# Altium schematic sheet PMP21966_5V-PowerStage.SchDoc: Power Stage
size 431 x 279 mm; Date: Not shown in title block; ApprovedBy: Not shown in title block; CheckedBy: Not shown in title block; Author: Not shown in title block; CompanyName: Not shown in title block; DrawnBy: Tiger Z; Engineer: Not shown in title block; Organization: Not shown in title block; Address1: Not shown in title block; Address2: Not shown in title block; Address3: Not shown in title block; Address4: Not shown in title block; DocumentNumber: 4; Revision: Use project parameter SCH_Rev; SheetNumber: 2; SheetTotal: 3; PageSetup: Record=PageOptions¦CenterHorizontal=True¦CenterVertical=True¦PrintScale=1.00¦XCorrection=1.00¦YCorrection=1.00¦PrintKind=0¦BorderSize=5000000¦LeftOffset=0¦BottomOffset=0¦Orientation=2¦PaperLength=1000¦PaperWidth=1000¦Scale=100¦PaperSource=15¦PrintQuality=600¦MediaType=1¦DitherType=10¦PaperKind=Letter¦PrintScaleMode=1
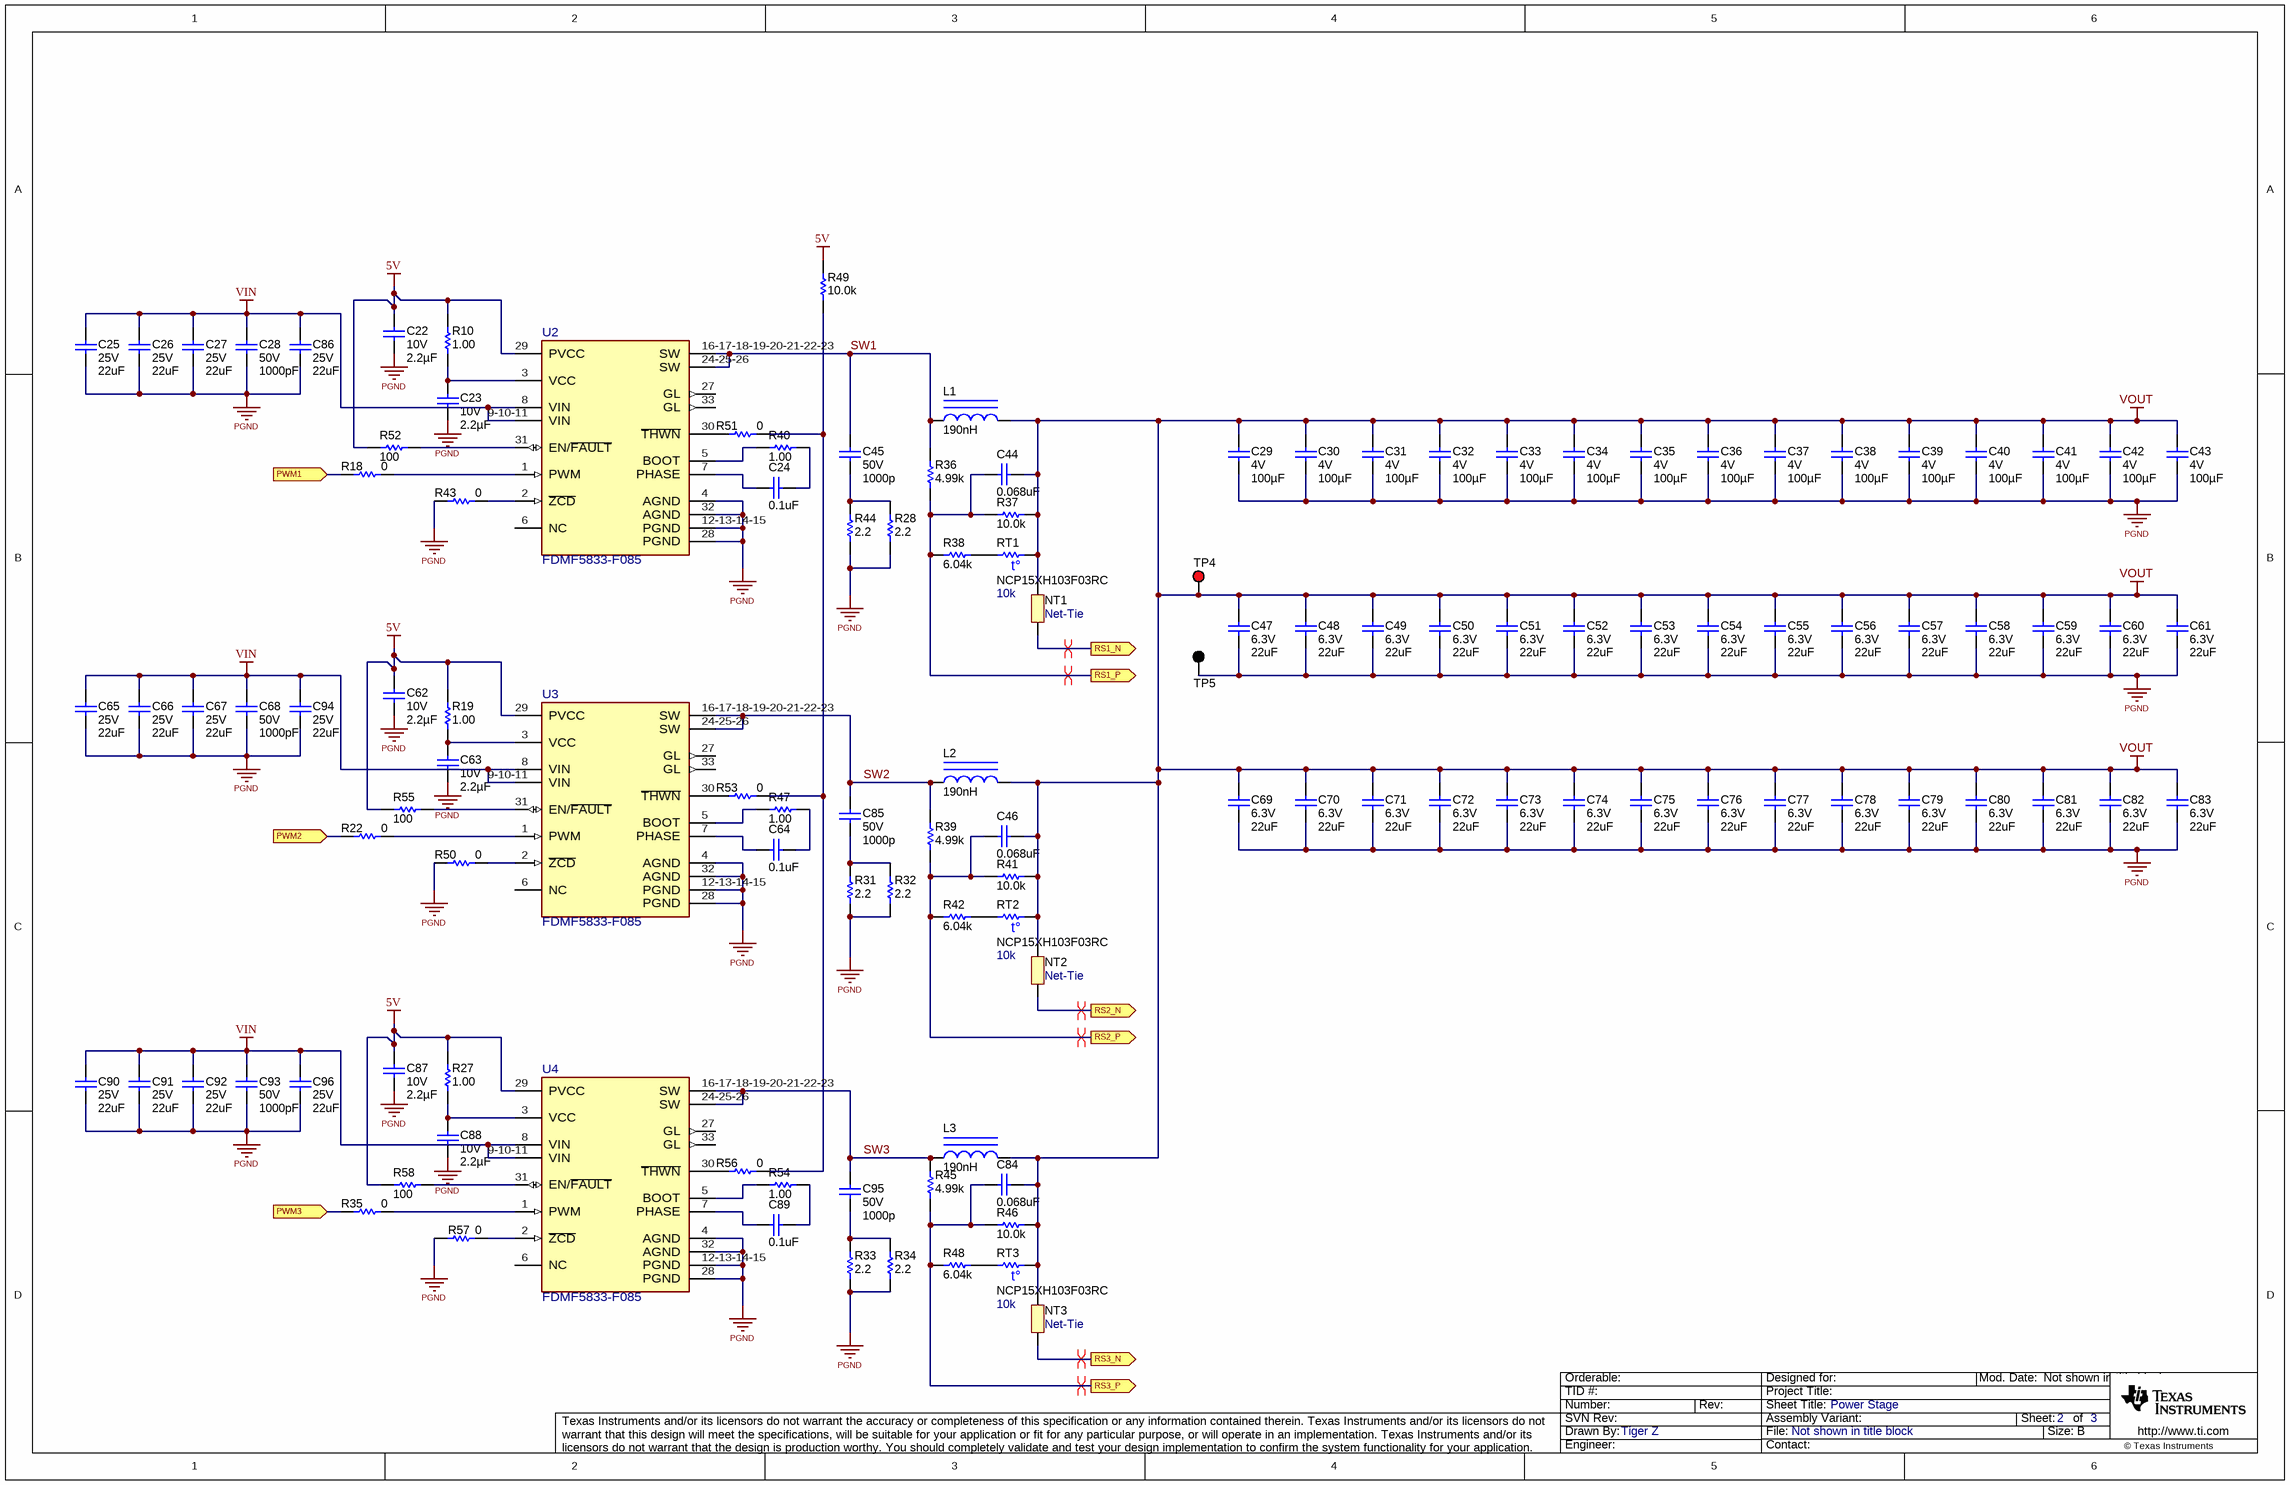
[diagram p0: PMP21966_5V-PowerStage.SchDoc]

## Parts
C22  VDC_V: 10V  ValueDisplayed: 2.2µF  [0603S]  (hidden comment: GRM188R71A225KE15J)
C23  VDC_V: 10V  ValueDisplayed: 2.2µF  [0603S]  (hidden comment: GRM188R71A225KE15J)
C24  ValueDisplayed: 0.1uF  [0402S]  (hidden comment: CGA2B3X7R1H104K050BB)
C25  VDC_V: 25V  ValueDisplayed: 22uF  [1210_270]  (hidden comment: TMK325B7226KMHT)
C26  VDC_V: 25V  ValueDisplayed: 22uF  [1210_270]  (hidden comment: TMK325B7226KMHT)
C27  VDC_V: 25V  ValueDisplayed: 22uF  [1210_270]  (hidden comment: TMK325B7226KMHT)
C28  VDC_V: 50V  ValueDisplayed: 1000pF  [0402S]  (hidden comment: GRM155R71H102KA01D)
C29  VDC_V: 4V  ValueDisplayed: 100µF  [1210_280]  (hidden comment: GCM32ED70G107M)
C30  VDC_V: 4V  ValueDisplayed: 100µF  [1210_280]  (hidden comment: GCM32ED70G107M)
C31  VDC_V: 4V  ValueDisplayed: 100µF  [1210_280]  (hidden comment: GCM32ED70G107M)
C32  VDC_V: 4V  ValueDisplayed: 100µF  [1210_280]  (hidden comment: GCM32ED70G107M)
C33  VDC_V: 4V  ValueDisplayed: 100µF  [1210_280]  (hidden comment: GCM32ED70G107M)
C34  VDC_V: 4V  ValueDisplayed: 100µF  [1210_280]  (hidden comment: GCM32ED70G107M)
C35  VDC_V: 4V  ValueDisplayed: 100µF  [1210_280]  (hidden comment: GCM32ED70G107M)
C36  VDC_V: 4V  ValueDisplayed: 100µF  [1210_280]  (hidden comment: GCM32ED70G107M)
C37  VDC_V: 4V  ValueDisplayed: 100µF  [1210_280]  (hidden comment: GCM32ED70G107M)
C38  VDC_V: 4V  ValueDisplayed: 100µF  [1210_280]  (hidden comment: GCM32ED70G107M)
C39  VDC_V: 4V  ValueDisplayed: 100µF  [1210_280]  (hidden comment: GCM32ED70G107M)
C40  VDC_V: 4V  ValueDisplayed: 100µF  [1210_280]  (hidden comment: GCM32ED70G107M)
C41  VDC_V: 4V  ValueDisplayed: 100µF  [1210_280]  (hidden comment: GCM32ED70G107M)
C42  VDC_V: 4V  ValueDisplayed: 100µF  [1210_280]  (hidden comment: GCM32ED70G107M)
C43  VDC_V: 4V  ValueDisplayed: 100µF  [1210_280]  (hidden comment: GCM32ED70G107M)
C44  ValueDisplayed: 0.068uF  [0402S]  (hidden comment: C1005X7R1H683K050BB)
C45  VDC_V: 50V  ValueDisplayed: 1000p  [0402S]  (hidden comment: GRM1555C1H102FA01D)
C46  ValueDisplayed: 0.068uF  [0402S]  (hidden comment: C1005X7R1H683K050BB)
C47  VDC_V: 6.3V  ValueDisplayed: 22uF  [0805_HV]  (hidden comment: GCM21BD70J226ME36L)
C48  VDC_V: 6.3V  ValueDisplayed: 22uF  [0805_HV]  (hidden comment: GCM21BD70J226ME36L)
C49  VDC_V: 6.3V  ValueDisplayed: 22uF  [0805_HV]  (hidden comment: GCM21BD70J226ME36L)
C50  VDC_V: 6.3V  ValueDisplayed: 22uF  [0805_HV]  (hidden comment: GCM21BD70J226ME36L)
C51  VDC_V: 6.3V  ValueDisplayed: 22uF  [0805_HV]  (hidden comment: GCM21BD70J226ME36L)
C52  VDC_V: 6.3V  ValueDisplayed: 22uF  [0805_HV]  (hidden comment: GCM21BD70J226ME36L)
C53  VDC_V: 6.3V  ValueDisplayed: 22uF  [0805_HV]  (hidden comment: GCM21BD70J226ME36L)
C54  VDC_V: 6.3V  ValueDisplayed: 22uF  [0805_HV]  (hidden comment: GCM21BD70J226ME36L)
C55  VDC_V: 6.3V  ValueDisplayed: 22uF  [0805_HV]  (hidden comment: GCM21BD70J226ME36L)
C56  VDC_V: 6.3V  ValueDisplayed: 22uF  [0805_HV]  (hidden comment: GCM21BD70J226ME36L)
C57  VDC_V: 6.3V  ValueDisplayed: 22uF  [0805_HV]  (hidden comment: GCM21BD70J226ME36L)
C58  VDC_V: 6.3V  ValueDisplayed: 22uF  [0805_HV]  (hidden comment: GCM21BD70J226ME36L)
C59  VDC_V: 6.3V  ValueDisplayed: 22uF  [0805_HV]  (hidden comment: GCM21BD70J226ME36L)
C60  VDC_V: 6.3V  ValueDisplayed: 22uF  [0805_HV]  (hidden comment: GCM21BD70J226ME36L)
C61  VDC_V: 6.3V  ValueDisplayed: 22uF  [0805_HV]  (hidden comment: GCM21BD70J226ME36L)
C62  VDC_V: 10V  ValueDisplayed: 2.2µF  [0603S]  (hidden comment: GRM188R71A225KE15J)
C63  VDC_V: 10V  ValueDisplayed: 2.2µF  [0603S]  (hidden comment: GRM188R71A225KE15J)
C64  ValueDisplayed: 0.1uF  [0402S]  (hidden comment: CGA2B3X7R1H104K050BB)
C65  VDC_V: 25V  ValueDisplayed: 22uF  [1210_270]  (hidden comment: TMK325B7226KMHT)
C66  VDC_V: 25V  ValueDisplayed: 22uF  [1210_270]  (hidden comment: TMK325B7226KMHT)
C67  VDC_V: 25V  ValueDisplayed: 22uF  [1210_270]  (hidden comment: TMK325B7226KMHT)
C68  VDC_V: 50V  ValueDisplayed: 1000pF  [0402S]  (hidden comment: GRM155R71H102KA01D)
C69  VDC_V: 6.3V  ValueDisplayed: 22uF  [0805_HV]  (hidden comment: GCM21BD70J226ME36L)
C70  VDC_V: 6.3V  ValueDisplayed: 22uF  [0805_HV]  (hidden comment: GCM21BD70J226ME36L)
C71  VDC_V: 6.3V  ValueDisplayed: 22uF  [0805_HV]  (hidden comment: GCM21BD70J226ME36L)
C72  VDC_V: 6.3V  ValueDisplayed: 22uF  [0805_HV]  (hidden comment: GCM21BD70J226ME36L)
C73  VDC_V: 6.3V  ValueDisplayed: 22uF  [0805_HV]  (hidden comment: GCM21BD70J226ME36L)
C74  VDC_V: 6.3V  ValueDisplayed: 22uF  [0805_HV]  (hidden comment: GCM21BD70J226ME36L)
C75  VDC_V: 6.3V  ValueDisplayed: 22uF  [0805_HV]  (hidden comment: GCM21BD70J226ME36L)
C76  VDC_V: 6.3V  ValueDisplayed: 22uF  [0805_HV]  (hidden comment: GCM21BD70J226ME36L)
C77  VDC_V: 6.3V  ValueDisplayed: 22uF  [0805_HV]  (hidden comment: GCM21BD70J226ME36L)
C78  VDC_V: 6.3V  ValueDisplayed: 22uF  [0805_HV]  (hidden comment: GCM21BD70J226ME36L)
C79  VDC_V: 6.3V  ValueDisplayed: 22uF  [0805_HV]  (hidden comment: GCM21BD70J226ME36L)
C80  VDC_V: 6.3V  ValueDisplayed: 22uF  [0805_HV]  (hidden comment: GCM21BD70J226ME36L)
C81  VDC_V: 6.3V  ValueDisplayed: 22uF  [0805_HV]  (hidden comment: GCM21BD70J226ME36L)
C82  VDC_V: 6.3V  ValueDisplayed: 22uF  [0805_HV]  (hidden comment: GCM21BD70J226ME36L)
C83  VDC_V: 6.3V  ValueDisplayed: 22uF  [0805_HV]  (hidden comment: GCM21BD70J226ME36L)
C84  ValueDisplayed: 0.068uF  [0402S]  (hidden comment: C1005X7R1H683K050BB)
C85  VDC_V: 50V  ValueDisplayed: 1000p  [0402S]  (hidden comment: GRM1555C1H102FA01D)
C86  VDC_V: 25V  ValueDisplayed: 22uF  [1210_270]  (hidden comment: TMK325B7226KMHT)
C87  VDC_V: 10V  ValueDisplayed: 2.2µF  [0603S]  (hidden comment: GRM188R71A225KE15J)
C88  VDC_V: 10V  ValueDisplayed: 2.2µF  [0603S]  (hidden comment: GRM188R71A225KE15J)
C89  ValueDisplayed: 0.1uF  [0402S]  (hidden comment: CGA2B3X7R1H104K050BB)
C90  VDC_V: 25V  ValueDisplayed: 22uF  [1210_270]  (hidden comment: TMK325B7226KMHT)
C91  VDC_V: 25V  ValueDisplayed: 22uF  [1210_270]  (hidden comment: TMK325B7226KMHT)
C92  VDC_V: 25V  ValueDisplayed: 22uF  [1210_270]  (hidden comment: TMK325B7226KMHT)
C93  VDC_V: 50V  ValueDisplayed: 1000pF  [0402S]  (hidden comment: GRM155R71H102KA01D)
C94  VDC_V: 25V  ValueDisplayed: 22uF  [1210_270]  (hidden comment: TMK325B7226KMHT)
C95  VDC_V: 50V  ValueDisplayed: 1000p  [0402S]  (hidden comment: GRM1555C1H102FA01D)
C96  VDC_V: 25V  ValueDisplayed: 22uF  [1210_270]  (hidden comment: TMK325B7226KMHT)
L1  ValueDisplayed: 190nH  [IHLP-4040DZ]  (hidden comment: IHLP4040DZERR19M11)
L2  ValueDisplayed: 190nH  [IHLP-4040DZ]  (hidden comment: IHLP4040DZERR19M11)
L3  ValueDisplayed: 190nH  [IHLP-4040DZ]  (hidden comment: IHLP4040DZERR19M11)
NT1  Net-Tie  [Net-Tie_10mil]  (net tie, no BOM)
NT2  Net-Tie  [Net-Tie_10mil]  (net tie, no BOM)
NT3  Net-Tie  [Net-Tie_10mil]  (net tie, no BOM)
R10  ValueDisplayed: 1.00  [0402S]  (hidden comment: CRCW04021R00FKED)
R18  ValueDisplayed: 0  [0402S]  (hidden comment: CRCW04020000Z0ED)
R19  ValueDisplayed: 1.00  [0402S]  (hidden comment: CRCW04021R00FKED)
R22  ValueDisplayed: 0  [0402S]  (hidden comment: CRCW04020000Z0ED)
R27  ValueDisplayed: 1.00  [0402S]  (hidden comment: CRCW04021R00FKED)
R28  ValueDisplayed: 2.2  [0603S]  (hidden comment: CRCW06032R20JNEA)
R31  ValueDisplayed: 2.2  [0603S]  (hidden comment: CRCW06032R20JNEA)
R32  ValueDisplayed: 2.2  [0603S]  (hidden comment: CRCW06032R20JNEA)
R33  ValueDisplayed: 2.2  [0603S]  (hidden comment: CRCW06032R20JNEA)
R34  ValueDisplayed: 2.2  [0603S]  (hidden comment: CRCW06032R20JNEA)
R35  ValueDisplayed: 0  [0402S]  (hidden comment: CRCW04020000Z0ED)
R36  ValueDisplayed: 4.99k  [0402S]  (hidden comment: CRCW04024K99FKED)
R37  ValueDisplayed: 10.0k  [0402S]  (hidden comment: CRCW040210K0FKED)
R38  ValueDisplayed: 6.04k  [0402S]  (hidden comment: CRCW04026K04FKED)
R39  ValueDisplayed: 4.99k  [0402S]  (hidden comment: CRCW04024K99FKED)
R40  ValueDisplayed: 1.00  [0402S]  (hidden comment: CRCW04021R00FKED)
R41  ValueDisplayed: 10.0k  [0402S]  (hidden comment: CRCW040210K0FKED)
R42  ValueDisplayed: 6.04k  [0402S]  (hidden comment: CRCW04026K04FKED)
R43  ValueDisplayed: 0  [0402S]  (hidden comment: CRCW04020000Z0ED)
R44  ValueDisplayed: 2.2  [0603S]  (hidden comment: CRCW06032R20JNEA)
R45  ValueDisplayed: 4.99k  [0402S]  (hidden comment: CRCW04024K99FKED)
R46  ValueDisplayed: 10.0k  [0402S]  (hidden comment: CRCW040210K0FKED)
R47  ValueDisplayed: 1.00  [0402S]  (hidden comment: CRCW04021R00FKED)
R48  ValueDisplayed: 6.04k  [0402S]  (hidden comment: CRCW04026K04FKED)
R49  ValueDisplayed: 10.0k  [0402S]  (hidden comment: CRCW040210K0FKED)
R50  ValueDisplayed: 0  [0402S]  (hidden comment: CRCW04020000Z0ED)
R51  ValueDisplayed: 0  [0402S]  (hidden comment: CRCW04020000Z0ED)
R52  ValueDisplayed: 100  [0402S]  (hidden comment: CRCW0402100RFKED)
R53  ValueDisplayed: 0  [0402S]  (hidden comment: CRCW04020000Z0ED)
R54  ValueDisplayed: 1.00  [0402S]  (hidden comment: CRCW04021R00FKED)
R55  ValueDisplayed: 100  [0402S]  (hidden comment: CRCW0402100RFKED)
R56  ValueDisplayed: 0  [0402S]  (hidden comment: CRCW04020000Z0ED)
R57  ValueDisplayed: 0  [0402S]  (hidden comment: CRCW04020000Z0ED)
R58  ValueDisplayed: 100  [0402S]  (hidden comment: CRCW0402100RFKED)
RT1  NCP15XH103F03RC  value 10k  [0402S]
RT2  NCP15XH103F03RC  value 10k  [0402S]
RT3  NCP15XH103F03RC  value 10k  [0402S]
TP4  5000  [Keystone5000]  (value not drawn)
TP5  5001  [Keystone5001]  (value not drawn)
U2  FDMF5833-F085  [FP-FDMF5833-F085_PQFN31-MFG]
U3  FDMF5833-F085  [FP-FDMF5833-F085_PQFN31-MFG]
U4  FDMF5833-F085  [FP-FDMF5833-F085_PQFN31-MFG]

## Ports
PWM1 (in), PWM2 (in), PWM3 (in), RS1_N (out), RS1_P (out), RS2_N (out), RS2_P (out), RS3_N (out), RS3_P (out)

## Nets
5V: C22.1 C62.1 C87.1 R10.2 R19.2 R27.2 R49.1 R52.1 R55.1 R58.1 U2.29(PVCC) U3.29(PVCC) U4.29(PVCC)
PGND: C22.2 C23.2 C25.2 C26.2 C27.2 C28.2 C29.2 C30.2 C31.2 C32.2 C33.2 C34.2 C35.2 C36.2 C37.2 C38.2 C39.2 C40.2 C41.2 C42.2 C43.2 C47.2 C48.2 C49.2 C50.2 C51.2 C52.2 C53.2 C54.2 C55.2 C56.2 C57.2 C58.2 C59.2 C60.2 C61.2 C62.2 C63.2 C65.2 C66.2 C67.2 C68.2 C69.2 C70.2 C71.2 C72.2 C73.2 C74.2 C75.2 C76.2 C77.2 C78.2 C79.2 C80.2 C81.2 C82.2 C83.2 C86.2 C87.2 C88.2 C90.2 C91.2 C92.2 C93.2 C94.2 C96.2 R28.1 R31.1 R32.1 R33.1 R34.1 R43.1 R44.1 R50.1 R57.1 TP5.1 U2.4(AGND) U2.12-13-14-15(PGND) U2.28(PGND) U2.32(AGND) U3.4(AGND) U3.12-13-14-15(PGND) U3.28(PGND) U3.32(AGND) U4.4(AGND) U4.12-13-14-15(PGND) U4.28(PGND) U4.32(AGND)
VIN: C25.1 C26.1 C27.1 C28.1 C65.1 C66.1 C67.1 C68.1 C86.1 C90.1 C91.1 C92.1 C93.1 C94.1 C96.1 U2.8(VIN) U2.9-10-11(VIN) U3.8(VIN) U3.9-10-11(VIN) U4.8(VIN) U4.9-10-11(VIN)
VOUT: C29.1 C30.1 C31.1 C32.1 C33.1 C34.1 C35.1 C36.1 C37.1 C38.1 C39.1 C40.1 C41.1 C42.1 C43.1 C44.2 C46.2 C47.1 C48.1 C49.1 C50.1 C51.1 C52.1 C53.1 C54.1 C55.1 C56.1 C57.1 C58.1 C59.1 C60.1 C61.1 C69.1 C70.1 C71.1 C72.1 C73.1 C74.1 C75.1 C76.1 C77.1 C78.1 C79.1 C80.1 C81.1 C82.1 C83.1 C84.2 L1.2 L2.2 L3.2 NT1.2 NT2.2 NT3.2 R37.1 R41.1 R46.1 RT1.2 RT2.2 RT3.2 TP4.1
PWM1: R18.1 ; port PWM1
PWM2: R22.1 ; port PWM2
PWM3: R35.1 ; port PWM3
RS1_N: NT1.1 ; port RS1_N
RS1_P: C44.1 R36.2 R37.2 R38.2 ; port RS1_P
RS2_N: NT2.1 ; port RS2_N
RS2_P: C46.1 R39.2 R41.2 R42.2 ; port RS2_P
RS3_N: NT3.1 ; port RS3_N
RS3_P: C84.1 R45.2 R46.2 R48.2 ; port RS3_P
SW1: C45.1 L1.1 R36.1 U2.16-17-18-19-20-21-22-23(SW) U2.24-25-26(SW)
SW2: C85.1 L2.1 R39.1 U3.16-17-18-19-20-21-22-23(SW) U3.24-25-26(SW)
SW3: C95.1 L3.1 R45.1 U4.16-17-18-19-20-21-22-23(SW) U4.24-25-26(SW)
NetC23_1: C23.1 R10.1 U2.3(VCC)
NetC24_1: C24.1 U2.7(PHASE)
NetC24_2: C24.2 R40.2
NetC45_2: C45.2 R28.2 R44.2
NetC63_1: C63.1 R19.1 U3.3(VCC)
NetC64_1: C64.1 U3.7(PHASE)
NetC64_2: C64.2 R47.2
NetC85_2: C85.2 R31.2 R32.2
NetC88_1: C88.1 R27.1 U4.3(VCC)
NetC89_1: C89.1 U4.7(PHASE)
NetC89_2: C89.2 R54.2
NetC95_2: C95.2 R33.2 R34.2
NetR18_2: R18.2 U2.1(PWM)
NetR22_2: R22.2 U3.1(PWM)
NetR35_2: R35.2 U4.1(PWM)
NetR38_1: R38.1 RT1.1
NetR40_1: R40.1 U2.5(BOOT)
NetR42_1: R42.1 RT2.1
NetR43_2: R43.2 U2.2(~{ZCD})
NetR47_1: R47.1 U3.5(BOOT)
NetR48_1: R48.1 RT3.1
NetR49_2: R49.2 R51.2 R53.2 R56.2
NetR50_2: R50.2 U3.2(~{ZCD})
NetR51_1: R51.1 U2.30(~{THWN})
NetR52_2: R52.2 U2.31(EN/~{FAULT})
NetR53_1: R53.1 U3.30(~{THWN})
NetR54_1: R54.1 U4.5(BOOT)
NetR55_2: R55.2 U3.31(EN/~{FAULT})
NetR56_1: R56.1 U4.30(~{THWN})
NetR57_2: R57.2 U4.2(~{ZCD})
NetR58_2: R58.2 U4.31(EN/~{FAULT})

Not connected (* = marked no-connect by the designer): U2 6(NC) 27(GL) 33(GL); U3 6(NC) 27(GL) 33(GL); U4 6(NC) 27(GL) 33(GL)

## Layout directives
differential pair: RS1_N, RS1_P, RS2_N, RS2_P, RS3_N, RS3_P

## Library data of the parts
C22 C23 C62 C63 C87 C88 = CMP-0084284-1: CAP, CERM, 2.2 µF, 10 V,+/- 10%, X7R, AEC-Q200 Grade 1, 0603; Manufacturer: MuRata; SizeAreaWB_mm2: 4.68; Polarized: N; AEC Qualified: Y; SizeX_mm: 1.6; SizeZ_mm: 1; SizeY_mm: 0.8; U/M: EA; TaMin_C: -55°C; Value: 2.2uF; Cap_Case: 0603; AEC Category: Q200; TaMax_C: 125°C; SizeArea_mm2: 1.28
C24 C64 C89 = CMP-0006325-2: CAP, CERM, 0.1 uF, 50 V, +/- 10%, X7R, AEC-Q200 Grade 1, 0402; Manufacturer: TDK; TaMin_C: -55°C; ESR_ohm: 0.039064; Polarized: N; SizeAreaWB_mm2: 3; Value1: 0.039064 ohm; U/M: EA; Value: 0.1uF; TaMax_C: 125°C; SizeZ_mm: 0.6; SizeX_mm: 1; SizeY_mm: 0.5; Cap_Case: 0402; Value2: 50V; CompType: Capacitor; AEC Qualified: Y; Cap_F: 100nF; IRMS_A: 8.14669dA; AEC Category: Q200
C25-C27 C65-C67 C86 C90-C92 C94 C96 = CMP-0009255-2: CAP, CERM, 22 uF, 25 V, +/- 10%, X7R, AEC-Q200 Grade 1, 1210; Manufacturer: Taiyo Yuden; Cap_F: 22µF; SizeAreaWB_mm2: 14.7; SizeArea_mm2: 8; AEC Qualified: Y; AEC Category: Q200; Value: 22uF; TaMax_C: 125°C; SizeZ_mm: 2.7; AEC Grade: 1; Polarized: N; TaMin_C: -55°C; SizeY_mm: 2.5; U/M: EA; SizeX_mm: 3.2; Cap_Case: 1210; Value1: Unknown
C28 C68 C93 = CMP-0006673-2: CAP, CERM, 1000 pF, 50 V, +/- 10%, X7R, 0402; Manufacturer: MuRata; TaMin_C: -55°C; Polarized: N; SizeAreaWB_mm2: 3; Value1: Unknown; U/M: EA; Value: 1000pF; TaMax_C: 125°C; SizeZ_mm: 0.6; SizeX_mm: 1; SizeY_mm: 0.5; Cap_Case: 0402; Cap_F: 1nF; AEC Category: Q200
C29-C43 = CMP-0082631-1: CAP, CERM, 100 µF, 4 V,+/- 20%, X7T, 1210; Manufacturer: MuRata; SizeAreaWB_mm2: 14.7; SizeArea_mm2: 8; AEC Qualified: N; AEC Category: Q200; Value: 100uF; SizeZ_mm: 2.8; SizeY_mm: 2.5; U/M: EA; CompType: Capacitor; SizeX_mm: 3.2; Cap_Case: 1210
C44 C46 C84 = CMP-0006299-2: CAP, CERM, 0.068 uF, 50 V, +/- 10%, X7R, 0402; Manufacturer: TDK; TaMin_C: -55°C; ESR_ohm: 0.05606; Polarized: N; SizeAreaWB_mm2: 3; Value1: 0.05606 ohm; U/M: EA; TaMax_C: 125°C; SizeZ_mm: 0.6; SizeX_mm: 1; SizeY_mm: 0.5; Cap_Case: 0402; Value2: 50V; Cap_F: 68nF; IRMS_A: 684.724mA; AEC Category: Q200
C45 C85 C95 = CMP-0006411-2: CAP, CERM, 1000 pF, 50 V, +/- 1%, C0G/NP0, 0402; Manufacturer: MuRata; TaMin_C: -55°C; Polarized: N; SizeAreaWB_mm2: 3; Value1: Unknown; U/M: EA; Value: 1000pF; TaMax_C: 125°C; SizeZ_mm: 0.6; SizeX_mm: 1; SizeY_mm: 0.5; Cap_Case: 0402; Cap_F: 1nF; AEC Category: Q200
C47 = CMP-0008015-1: CAP, CERM, 22 uF, 6.3 V, +/- 20%, X7T, AEC-Q200 Grade 1, 0805; Manufacturer: MuRata; TaMin_C: -55°C; Polarized: N; SizeAreaWB_mm2: 6.75; Value1: Unknown; U/M: EA; Value: 22uF; TaMax_C: 125°C; SizeZ_mm: 1.45; SizeX_mm: 2; SizeY_mm: 1.25; Cap_Case: 0805; SizeArea_mm2: 2.5; CompType: Capacitor; AEC Qualified: Y; Cap_F: 22µF; AEC Grade: 1; AEC Category: Q200
C48-C61 C69-C83 = CMP-0008015-1: CAP, CERM, 22 uF, 6.3 V, +/- 20%, X7T, AEC-Q200 Grade 1, 0805; Manufacturer: MuRata; TaMin_C: -55°C; Polarized: N; SizeAreaWB_mm2: 6.75; Value1: Unknown; U/M: EA; Value: 22uF; TaMax_C: 125°C; SizeZ_mm: 1.45; SizeX_mm: 2; SizeY_mm: 1.25; Cap_Case: 0805; SizeArea_mm2: 2.5; AEC Qualified: Y; Cap_F: 22µF; AEC Grade: 1; AEC Category: Q200
L1-L3 = CMP-0063459-1: Inductor, Shielded, Powdered Iron, 190 nH, 40 A, 0.0008 ohm, SMD; Manufacturer: Vishay-Dale; Isat: 46A @ 20% inductance drop; Irms: 40A @ 40C rise; Green_Lifecycle: Active; SizeAreaWB_mm2: 166.05; DCR_ohm: 800µ; Green_REACh: Passed; Value: 190nH; Imax_A: 40A; SizeZ_mm: 4; SizeX_mm: 11.5; SizeY_mm: 10.3; SizeArea_mm2: 118.45; AEC Category: Q200
NT1-NT3 = CMP-0078142-2: Single point connection between nets.
R10 R19 R27 R40 R47 R54 = CMP-0026129-2: RES, 1.00, 1%, 0.063 W, AEC-Q200 Grade 0, 0402; Manufacturer: Vishay-Dale; Power_W: 63mW; TempCo: 100 ppm/C; Value_Code: 1R00; Value: 1.00; EIA_Code: E96; Res_ohm: 1; SizeY_mm: 0.5; SizeZ_mm: 0.6; Value2: 0.063W; AEC Qualified: Y; VDC_V: 50V; AEC Category: Q200; AEC Grade: 0
R18 R22 R35 R43 R50 R51 R53 R56 R57 = CMP-0026822-3: RES, 0, 5%, 0.063 W, AEC-Q200 Grade 0, 0402; Manufacturer: Vishay-Dale; Power_W: 63mW; TempCo: 200 ppm/C; Value_Code: 0000; Value: 0; EIA_Code: E24; SizeX_mm: 1; SizeY_mm: 0.5; SizeZ_mm: 0.6; Value2: 0.063W; AEC Qualified: Y; VDC_V: 50V; AEC Category: Q200
R28 R31-R34 R44 = CMP-0025777-4: RES, 2.2, 5%, 0.1 W, AEC-Q200 Grade 0, 0603; Manufacturer: Vishay-Dale; Power_W: 100mW; TempCo: 200 ppm/C; Value_Code: 2R20; Value: 2.2; EIA_Code: E24; SizeX_mm: 1.6; SizeY_mm: 0.8; SizeZ_mm: 1; Value2: 0.1W; SizeArea_mm2: 1.28; AEC Qualified: Y; VDC_V: 75V; AEC Category: Q200; AEC Grade: 0
R36 R39 R45 = CMP-0026414-2: RES, 4.99 k, 1%, 0.063 W, AEC-Q200 Grade 0, 0402; Manufacturer: Vishay-Dale; Power_W: 63mW; TempCo: 100 ppm/C; Value_Code: 4k99; Value: 4.99k; EIA_Code: E96; SizeX_mm: 1; SizeY_mm: 0.5; SizeZ_mm: 0.6; Value2: 0.063W; AEC Qualified: Y; VDC_V: 50V; AEC Category: Q200; AEC Grade: 0
R37 R41 R46 R49 = CMP-0025958-3: RES, 10.0 k, 1%, 0.063 W, AEC-Q200 Grade 0, 0402; Manufacturer: Vishay-Dale; Power_W: 63mW; TempCo: 100 ppm/C; Value_Code: 10k0; Value: 10.0k; EIA_Code: E96; Res_ohm: 10k; SizeX_mm: 1; SizeY_mm: 0.5; SizeZ_mm: 0.6; Value2: 0.063W; AEC Qualified: Y; VDC_V: 50V; AEC Category: Q200; AEC Grade: 0
R38 R42 R48 = CMP-0026512-2: RES, 6.04 k, 1%, 0.063 W, AEC-Q200 Grade 0, 0402; Manufacturer: Vishay-Dale; Power_W: 63mW; TempCo: 100 ppm/C; Value_Code: 6k04; Value: 6.04k; EIA_Code: E96; SizeX_mm: 1; SizeY_mm: 0.5; SizeZ_mm: 0.6; Value2: 0.063W; AEC Qualified: Y; VDC_V: 50V; AEC Category: Q200; AEC Grade: 0
R52 R55 R58 = CMP-0025951-3: RES, 100, 1%, 0.063 W, AEC-Q200 Grade 0, 0402; Manufacturer: Vishay-Dale; Power_W: 63mW; TempCo: 100 ppm/C; Value_Code: 100R; Value: 100; EIA_Code: E96; SizeX_mm: 1; SizeY_mm: 0.5; SizeZ_mm: 0.6; Value2: 0.063W; AEC Qualified: Y; VDC_V: 50V; AEC Category: Q200; AEC Grade: 0
RT1-RT3 = CMP-0002344-2: Thermistor NTC, 10.0k ohm, 1%, 0402; Manufacturer: MuRata; TaMax_C: 125°C; SizeX_mm: 1; SizeY_mm: 0.5; TaMin_C: -40°C; Power_W: 100mW; SizeZ_mm: 0.6; SizeAreaWB_mm2: 3; U/M: EA
TP4 = CMP-0055137-1: Test Point, Miniature, Red, TH; Manufacturer: Keystone; CNHeader: FALSE; Green_Lifecycle: Active; Green_REACh: Passed; ContactFinish: Silver; CT: TRUE
TP5 = CMP-0055138-1: Test Point, Miniature, Black, TH; Manufacturer: Keystone; CNHeader: FALSE; ContactFinish: Silver; CT: TRUE; Green_Lifecycle: Active; Green_REACh: Passed
U2-U4 = CMP-0087068-1: Smart Power Stage (SPS) Module with Integrated Thermal Warning and Thermal Shutdown; Manufacturer: ON Semiconductor; SizeZ_mm: 0.8mm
